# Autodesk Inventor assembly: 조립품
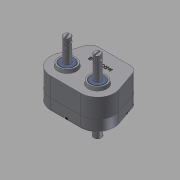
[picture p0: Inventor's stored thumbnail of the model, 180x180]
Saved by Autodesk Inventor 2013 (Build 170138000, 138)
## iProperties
Created: 2014-12
Part Number: 조립품
Document SubType Name: Assembly
Designer: WINDOWS7
Author: WINDOWS7
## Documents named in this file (14)
- C:\Users\WINDOWS7\Desktop\441209v1036\조립품.iam
- C:\Users\WINDOWS7\Desktop\441209v1036\본체.ipt
- C:\Users\WINDOWS7\Desktop\441209v1036\메인기어.ipt
- C:\Users\WINDOWS7\Desktop\441209v1036\오일시일-D-15.ipt
- C:\Users\WINDOWS7\Desktop\441209v1036\서브기어.ipt
- C:\Users\WINDOWS7\Desktop\441209v1036\베어링- 6202.ipt
- C:\Users\WINDOWS7\Desktop\441209v1036\멈춤링.ipt
- C:\Users\WINDOWS7\Desktop\441209v1036\커버.ipt
- C:\Users\WINDOWS7\Desktop\441209v1036\서브축.ipt
- C:\Users\WINDOWS7\Desktop\441209v1036\키5x5.ipt
- C:\Users\WINDOWS7\Desktop\441209v1036\메인축.ipt
- C:\Users\WINDOWS7\Desktop\441209v1036\베어링- 6203.ipt
- C:\Users\WINDOWS7\Desktop\441209v1036\오일시일-D-17.ipt
- C:\Users\WINDOWS7\Desktop\441209v1036\M 5 x 35.ipt
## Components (12 placed, 6 different names)
1. KS B 2804 D D - 15 30 7:1
2. KS B 2804 D D - 15 30 7:2
3. KS B 2023 6202 - 15 x 35 x 11:1
4. KS B 2023 6202 - 15 x 35 x 11:2
5. KS B 1336 17 x 1:1
6. KS B 1336 17 x 1:2
7. KS B 1336 17 x 1:3
8. KS B 2023 6203 - 17 x 40 x 12:1
9. KS B 2804 D D - 17 30 8:1
10. KS B 1003 - 미터 M 5 x 35:1
11. KS B 1003 - 미터 M 5 x 35:2
12. KS B 1003 - 미터 M 5 x 35:3
